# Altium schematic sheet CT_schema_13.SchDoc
size 389 x 385 mm
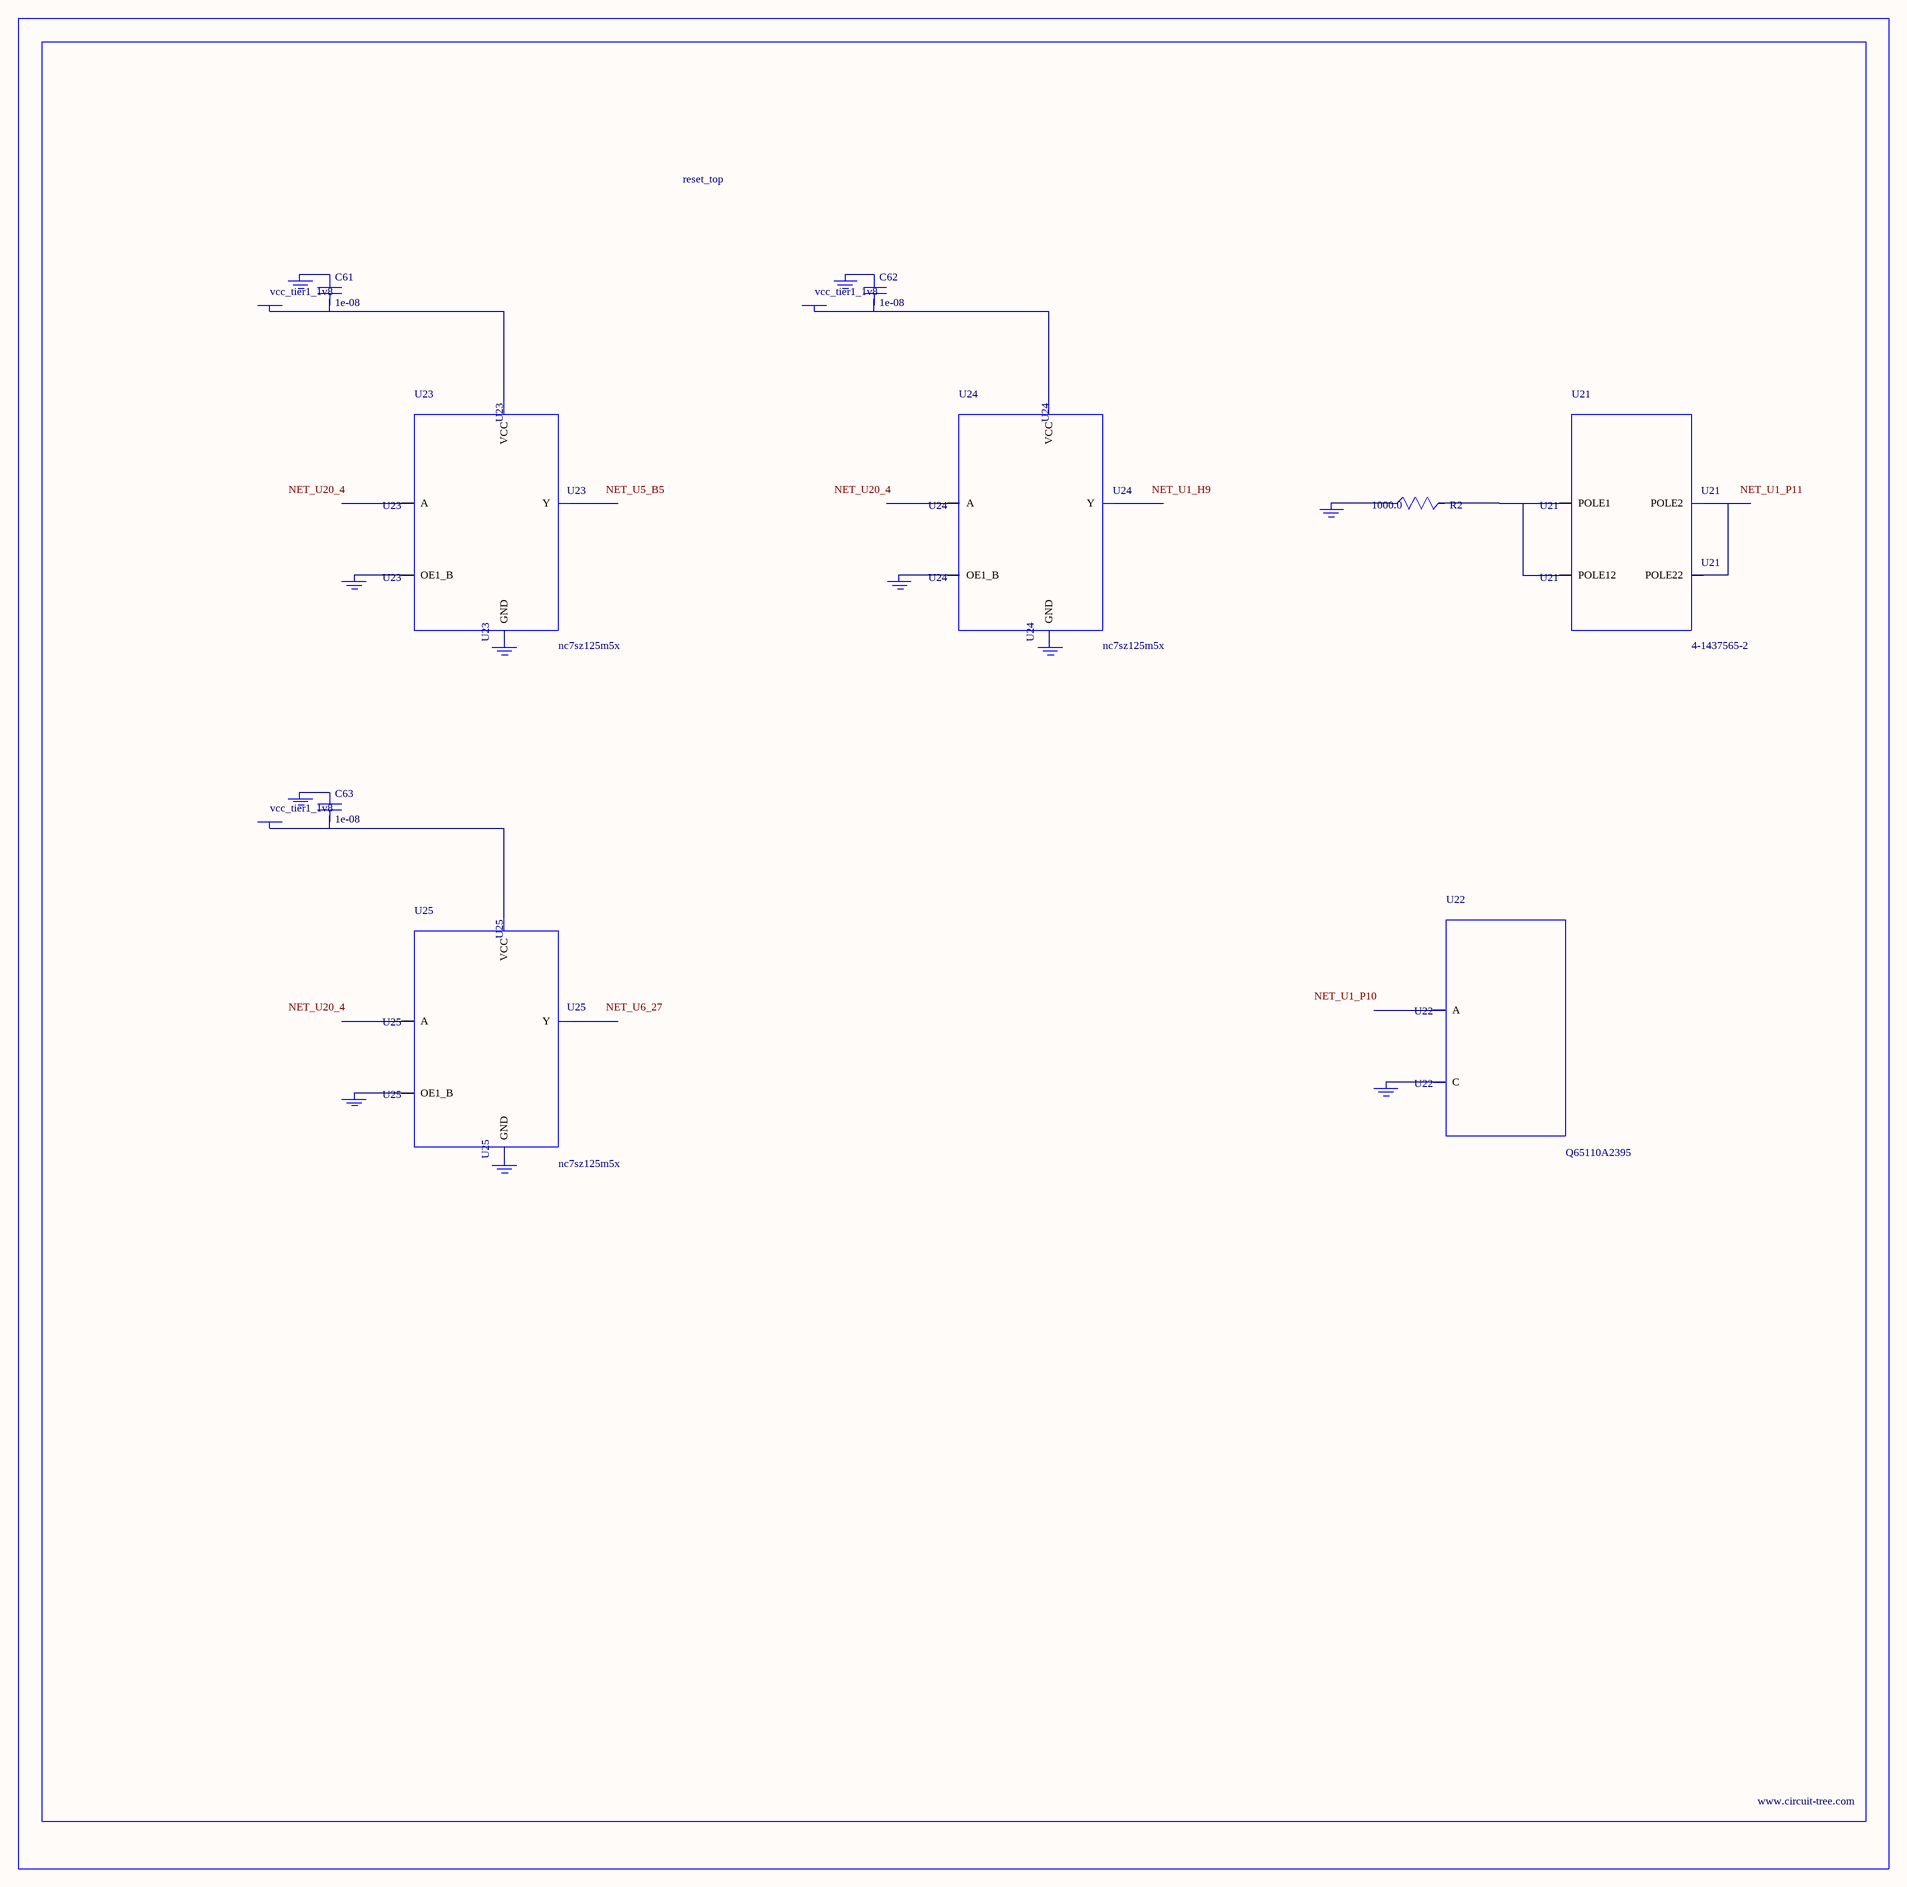
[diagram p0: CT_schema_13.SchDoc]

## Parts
BORDER12  (no value)
C61  1e-08  [C0402]
C62  1e-08  [C0402]
C63  1e-08  [C0402]
GND_INSTANCE_12_0  (no value)
GND_INSTANCE_12_1  (no value)
GND_INSTANCE_12_2  (no value)
GND_INSTANCE_12_3  (no value)
GND_INSTANCE_12_4  (no value)
GND_INSTANCE_12_5  (no value)
GND_INSTANCE_12_6  (no value)
GND_INSTANCE_12_7  (no value)
GND_INSTANCE_12_8  (no value)
GND_INSTANCE_12_9  (no value)
GND_INSTANCE_12_10  (no value)
POWER_INSTANCE_12_0  vcc_tier1_1v8
POWER_INSTANCE_12_1  vcc_tier1_1v8
POWER_INSTANCE_12_2  vcc_tier1_1v8
R2  1000.0  [R0603]
U21  4-1437565-2  [SW_4-1437565-2]
U22  Q65110A2395  [LGM67K-G1J2-24-Z]
U23  nc7sz125m5x  [NC7SZ125M5X]
U24  nc7sz125m5x  [NC7SZ125M5X]
U25  nc7sz125m5x  [NC7SZ125M5X]

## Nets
NetC61_1: C61.1 GND_INSTANCE_12_2.0(GND)
NetC61_2: C61.2 POWER_INSTANCE_12_0.0(PWR) U23.5(VCC)
NetC62_1: C62.1 GND_INSTANCE_12_5.0(GND)
NetC62_2: C62.2 POWER_INSTANCE_12_1.0(PWR) U24.5(VCC)
NetC63_1: C63.1 GND_INSTANCE_12_8.0(GND)
NetC63_2: C63.2 POWER_INSTANCE_12_2.0(PWR) U25.5(VCC)
NetGND_INSTANCE_12_0_0: GND_INSTANCE_12_0.0(GND) R2.1
NetGND_INSTANCE_12_1_0: GND_INSTANCE_12_1.0(GND) U22.C
NetGND_INSTANCE_12_3_0: GND_INSTANCE_12_3.0(GND) U23.1(OE1_B)
NetGND_INSTANCE_12_4_0: GND_INSTANCE_12_4.0(GND) U23.3(GND)
NetGND_INSTANCE_12_6_0: GND_INSTANCE_12_6.0(GND) U24.1(OE1_B)
NetGND_INSTANCE_12_7_0: GND_INSTANCE_12_7.0(GND) U24.3(GND)
NetGND_INSTANCE_12_9_0: GND_INSTANCE_12_9.0(GND) U25.1(OE1_B)
NetGND_INSTANCE_12_10_0: GND_INSTANCE_12_10.0(GND) U25.3(GND)
NetR2_2: R2.2 U21.1(POLE1) U21.2(POLE12)
NetU21_3: U21.3(POLE2) U21.4(POLE22)

Not connected (* = marked no-connect by the designer): U22 A; U23 2(A) 4(Y); U24 2(A) 4(Y); U25 2(A) 4(Y)

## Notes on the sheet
- Labels drawn without touching a wire or pin: NET_U1_H9, NET_U1_P10, NET_U1_P11, NET_U5_B5, NET_U6_27, NET_U20_4

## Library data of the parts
BORDER12 = BORDER_PAGE12
C61-C63 = C0402C103K3RAC
GND_INSTANCE_12_0-GND_INSTANCE_12_10 = GND
POWER_INSTANCE_12_0-POWER_INSTANCE_12_2 = PWR
R2 = RC0603JR-071KL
